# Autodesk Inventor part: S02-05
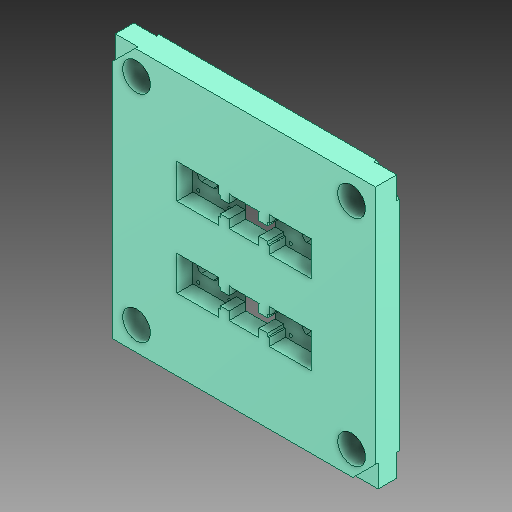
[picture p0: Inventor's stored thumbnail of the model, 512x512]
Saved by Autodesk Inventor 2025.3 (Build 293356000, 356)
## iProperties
Created: 2025-04
Part Number: S02-05
Material: Všeobecné
Document SubType Name: Modeling
Designer: Patrik
Density: 1 g/cm^3
Appearance: Výchozí
Description: Deska tvarová levá
Stock Number: F 50 /396 396/ 36/1730
Mass: 4884.07 g
Surface Area: 4811.56 cm^2
Volume: 4884.07 cm^3
User Status: 1730
Author: Patrik
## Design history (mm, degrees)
feature "Base1"
feature "Vyřezání2"
feature "Vyřezání3"
sketch "Náčrt2"
  geometry: L1 (121.5, -219.474)-(206.5, -219.474) reference; L2 (121.5, -304.474)-(121.5, -219.474) reference; L3 (206.5, -304.474)-(121.5, -304.474) reference; L4 (206.5, -219.474)-(206.5, -304.474) reference; L5 (186.5, -239.474)-(186.5, -284.474) reference; L6 (186.5, -284.474)-(141.5, -284.474) reference; L7 (141.5, -284.474)-(141.5, -239.474) reference; L8 (141.5, -239.474)-(186.5, -239.474) reference; L9 (121.5, -99.474)-(206.5, -99.474) reference; L10 (121.5, -184.474)-(121.5, -99.474) reference; L11 (206.5, -184.474)-(121.5, -184.474) reference; L12 (206.5, -99.474)-(206.5, -184.474) reference; L13 (186.5, -119.474)-(186.5, -164.474) reference; L14 (186.5, -164.474)-(141.5, -164.474) reference; L15 (141.5, -164.474)-(141.5, -119.474) reference; L16 (141.5, -119.474)-(186.5, -119.474) reference; 1 further point
extrude "Vysunutí2" cut sketch "Náčrt2" stored distance "d2" = 10; taper "d3" = 0 deg
chamfer "Zkosení1" distance "d4" = 1; stored, may be unused: second distance "d5" = 2, angle "d6" = 45 deg
feature "Vyřezání5"
sketch "Náčrt4"
  geometry: L1 (125.9, -287.974)-(62.9, -287.974) reference; L2 (62.9, -235.974)-(125.9, -235.974) reference; L3 (125.9, -167.974)-(62.9, -167.974) reference; L4 (62.9, -115.974)-(125.9, -115.974) reference; L5 (202.1, -287.974)-(265.1, -287.974) reference; L6 (265.1, -235.974)-(202.1, -235.974) reference; L7 (202.1, -167.974)-(265.1, -167.974) reference; L8 (265.1, -115.974)-(202.1, -115.974) reference; L9 (125.9, -235.974)-(62.9, -235.974) reference; L10 (62.9, -235.974)-(125.9, -235.974) reference; L11 (125.9, -276.974)-(125.9, -287.974) reference; L12 (125.9, -235.974)-(125.9, -246.974) reference; L13 (125.9, -156.974)-(125.9, -167.974) reference; L14 (125.9, -115.974)-(125.9, -126.974) reference; L15 (141.5, -131.974)-(128.425, -131.974) reference; L16 (128.425, -151.974)-(141.5, -151.974) reference; L17 (128.425, -271.974)-(141.5, -271.974) reference; L18 (141.5, -251.974)-(128.425, -251.974) reference; L19 (199.575, -271.974)-(186.5, -271.974) reference; L20 (202.1, -276.974)-(202.1, -287.974) reference; L21 (202.1, -235.974)-(202.1, -246.974) reference; L22 (186.5, -251.974)-(199.575, -251.974) reference; L23 (202.1, -156.974)-(202.1, -167.974) reference; L24 (202.1, -115.974)-(202.1, -126.974) reference; L25 (186.5, -131.974)-(199.575, -131.974) reference; L26 (199.575, -151.974)-(186.5, -151.974) reference; L27 (62.9, -287.974)-(62.9, -235.974); L28 (62.9, -167.974)-(62.9, -115.974); L29 (265.1, -287.974)-(265.1, -235.974); L30 (265.1, -167.974)-(265.1, -115.974); L31 (199.575, -271.974)-(202.1, -271.974); L32 (186.5, -251.974)-(202.1, -251.974) reference; L33 (199.575, -251.974)-(202.1, -251.974); L34 (186.5, -271.974)-(186.5, -251.974); L35 (202.1, -276.974)-(202.1, -271.974); L36 (202.1, -251.974)-(202.1, -246.974); L37 (128.425, -271.974)-(125.9, -271.974); L38 (128.425, -251.974)-(125.9, -251.974) reference; L39 (128.425, -251.974)-(125.9, -251.974); L40 (141.5, -271.974)-(141.5, -251.974); L41 (128.425, -151.974)-(125.9, -151.974); L42 (128.425, -131.974)-(125.9, -131.974); L43 (141.5, -151.974)-(141.5, -131.974); L44 (125.9, -156.974)-(125.9, -151.974); L45 (125.9, -131.974)-(125.9, -126.974); L46 (186.5, -151.974)-(186.5, -131.974); L47 (202.1, -151.974)-(186.5, -151.974) reference; L48 (199.575, -151.974)-(202.1, -151.974); L49 (199.575, -131.974)-(202.1, -131.974); L50 (202.1, -156.974)-(202.1, -151.974); L51 (202.1, -131.974)-(202.1, -126.974); L52 (125.9, -276.974)-(125.9, -271.974); L53 (125.9, -251.974)-(125.9, -246.974); L54 (128.43, -276.474)-(128.43, -271.974); L55 (128.43, -276.474)-(125.9, -276.474); L56 (128.43, -251.974)-(128.43, -247.474); L57 (128.43, -151.974)-(128.43, -156.474); L58 (128.43, -131.974)-(128.43, -127.474); L59 (128.43, -247.474)-(125.9, -247.474); L60 (128.43, -156.474)-(125.9, -156.474); L61 (128.43, -127.474)-(125.9, -127.474); L62 (199.57, -276.474)-(199.57, -271.974); L63 (199.57, -251.974)-(199.57, -247.474); L64 (199.57, -151.974)-(199.57, -156.474)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; 9 further points
  constraints: 80 end point, 21 perpendicular, 15 point on line, 13 collinear, 7 equal length, 7 vertical, 2 horizontal, 2 parallel
  dimensions: "d11" = 4.5 distance of L54.start L54.end; "d12" = 2.53 distance between parallel lines of L54 L52; "d13" = 2.53 distance between parallel lines of L35 L62 (= d12)
extrude "Vysunutí4" cut sketch "Náčrt4" stored distance "d9" = 10; taper "d10" = 0 deg
sketch "Náčrt5"
  geometry: L1 (71.9, -135.974)-(93.9, -135.974) reference; L2 (93.9, -147.974)-(71.9, -147.974) reference; L3 (256.1, -135.974)-(234.1, -135.974) reference; L4 (234.1, -147.974)-(256.1, -147.974) reference; L5 (256.1, -255.974)-(234.1, -255.974) reference; L6 (234.1, -267.974)-(256.1, -267.974) reference; L7 (71.9, -255.974)-(93.9, -255.974) reference; L8 (93.9, -267.974)-(71.9, -267.974) reference; A1 r 6 centre (93.9, -141.974) between (93.9, -147.974) and (93.9, -135.974) reference; A2 r 6 centre (71.9, -141.974) between (71.9, -135.974) and (71.9, -147.974) reference; A3 r 6 centre (256.1, -141.974) between (256.1, -147.974) and (256.1, -135.974) reference; A4 r 6 centre (234.1, -141.974) between (234.1, -135.974) and (234.1, -147.974) reference; A5 r 6 centre (256.1, -261.974) between (256.1, -267.974) and (256.1, -255.974) reference; A6 r 6 centre (234.1, -261.974) between (234.1, -255.974) and (234.1, -267.974) reference; A7 r 6 centre (93.9, -261.974) between (93.9, -267.974) and (93.9, -255.974) reference; A8 r 6 centre (71.9, -261.974) between (71.9, -255.974) and (71.9, -267.974) reference; A9 r 6 centre (75.9, -141.974) between (75.9, -135.974) and (75.9, -147.974); A10 r 6 centre (75.9, -261.974) between (75.9, -255.974) and (75.9, -267.974); A11 r 6 centre (252.1, -141.974) between (252.1, -147.974) and (252.1, -135.974); A12 r 6 centre (252.1, -261.974) between (252.1, -267.974) and (252.1, -255.974)
  constraints: 8 point on circle, 8 point on line, 4 centre point, 4 equal radius, 4 horizontal alignment
  dimensions: "d16" = 4 distance of A9.centre A2.centre; "d17" = 4 distance of A3.centre A11.centre; "d18" = 4 distance of A8.centre A10.centre; "d19" = 4 distance of A5.centre A12.centre
extrude "Vysunutí5" cut sketch "Náčrt5" stored distance "d14" = 10; taper "d15" = 0 deg
node "Těleso1"
node "Promítnutá smyčka2"
node "Promítnutá smyčka3"
node "Referenční1"
node "Referenční2"
node "Referenční3"
node "Referenční4"
node "Referenční5"
node "Referenční6"
node "Referenční7"
node "Referenční8"
node "Promítnutá smyčka5"
node "Referenční9"
node "Referenční10"
node "Referenční11"
node "Referenční12"
node "Referenční13"
node "Referenční14"
node "Referenční15"
node "Referenční16"
feature "Plocha4"
node "Povrch4"
feature "Plocha8"
node "Povrch8"
feature "Plocha10"
node "Povrch10"
